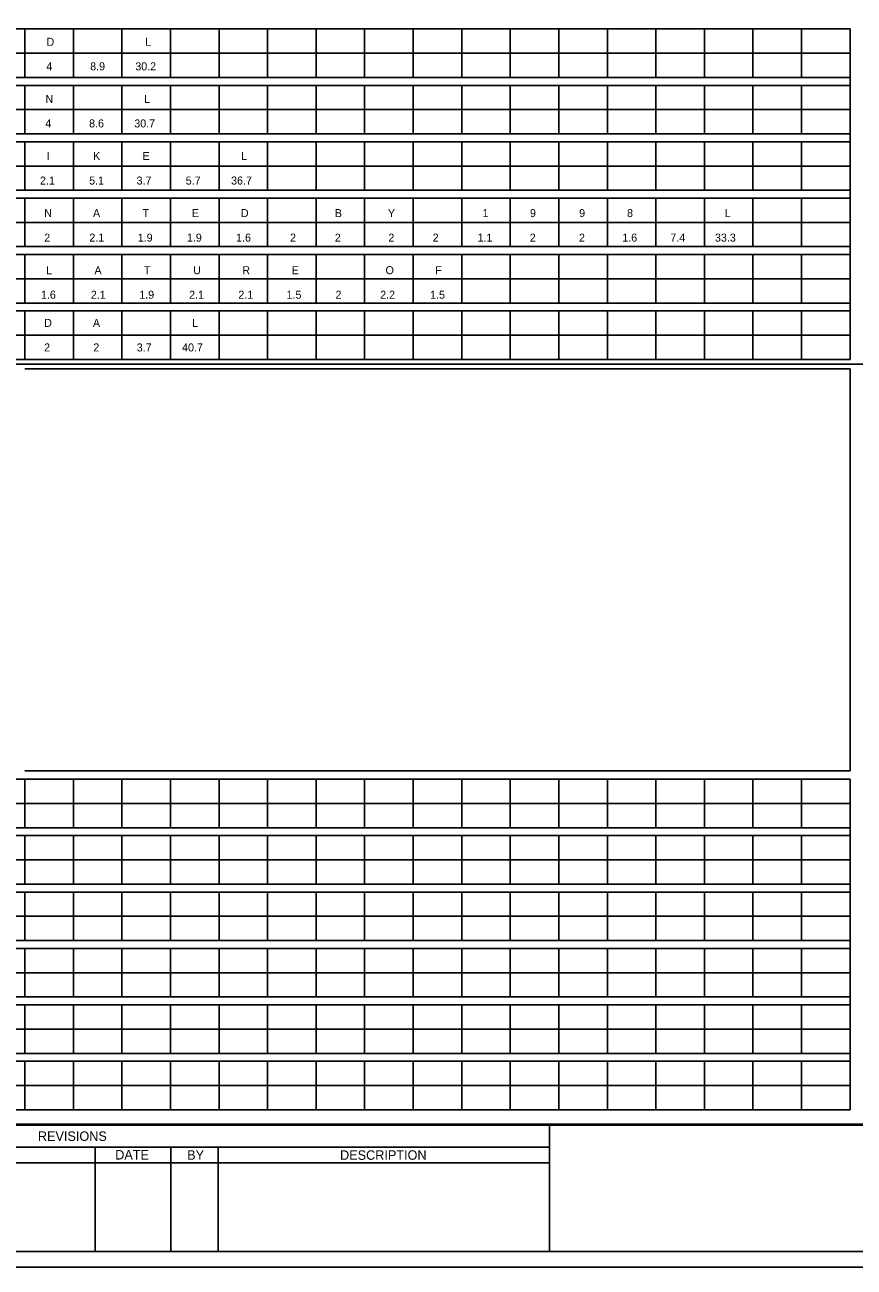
# Model space of a CAD drawing. Extents: x 17890628 to 17890844, y 17897693 to 17898031.
# Drawn here: x 17890726.4 to 17890772.1, y 17897907.6 to 17897976.1 of the extents above; entities that cross this region are included whole.
import ezdxf

# ---------------------------------------------------------------- set-up
doc = ezdxf.new("R2010")
doc.units = 0
for name, color, linetype in [('GSSign', 7, 'Continuous'), ('PlotBorder_dp', 7, 'Continuous'), ('SheetBorder_dp', 7, 'Continuous'), ('SheetLines_dp', 7, 'Continuous'), ('SheetLinesMisc2_dp', 7, 'Continuous'), ('TextMisc', 7, 'Continuous')]:
    doc.layers.add(name, color=color, linetype=linetype)

msp = doc.modelspace()

# ---------------------------------------------------------------- linework, layer by layer
at = {"layer": 'PlotBorder_dp'}
msp.add_lwpolyline([(17890700.471, 17897907.61), (17890843.989, 17897907.61), (17890843.989, 17897999.809), (17890700.471, 17897999.809)], close=True, dxfattribs=at)
at = {"layer": 'SheetBorder_dp'}
for p, q in [((17890705.254, 17897915.438), (17890839.205, 17897915.438)), ((17890705.254, 17897908.479), (17890839.205, 17897908.479))]:
    msp.add_line(p, q, dxfattribs=at)
at = {"layer": 'SheetLines_dp'}
for p, q in [((17890755.355, 17897915.438), (17890755.355, 17897908.479)), ((17890705.254, 17897914.22), (17890755.355, 17897914.22)), ((17890730.305, 17897914.22), (17890730.305, 17897908.479)), ((17890734.48, 17897914.22), (17890734.48, 17897908.479)), ((17890737.089, 17897914.22), (17890737.089, 17897908.479)), ((17890705.254, 17897913.35), (17890755.355, 17897913.35))]:
    msp.add_line(p, q, dxfattribs=at)
at = {"layer": 'SheetLinesMisc2_dp'}
for p, q in [((17890706.142, 17897975.843), (17890771.912, 17897975.843)), ((17890726.429, 17897975.843), (17890726.429, 17897973.171)), ((17890729.104, 17897975.843), (17890729.104, 17897973.171)), ((17890731.779, 17897975.843), (17890731.779, 17897973.171)), ((17890734.455, 17897975.843), (17890734.455, 17897973.171)), ((17890737.131, 17897975.843), (17890737.131, 17897973.171)), ((17890739.806, 17897975.843), (17890739.806, 17897973.171)), ((17890742.481, 17897975.843), (17890742.481, 17897973.171)), ((17890745.157, 17897975.843), (17890745.157, 17897973.171)), ((17890747.833, 17897975.843), (17890747.833, 17897973.171)), ((17890750.508, 17897975.843), (17890750.508, 17897973.171)), ((17890753.183, 17897975.843), (17890753.183, 17897973.171)), ((17890755.859, 17897975.843), (17890755.859, 17897973.171)), ((17890758.535, 17897975.843), (17890758.535, 17897973.171)), ((17890761.21, 17897975.843), (17890761.21, 17897973.171)), ((17890763.885, 17897975.843), (17890763.885, 17897973.171)), ((17890766.561, 17897975.843), (17890766.561, 17897973.171)), ((17890769.237, 17897975.843), (17890769.237, 17897973.171)), ((17890771.912, 17897957.633), (17890771.912, 17897975.843)), ((17890706.142, 17897974.507), (17890771.912, 17897974.507)), ((17890706.142, 17897973.171), (17890771.912, 17897973.171)), ((17890706.142, 17897972.735), (17890771.912, 17897972.735)), ((17890726.429, 17897972.735), (17890726.429, 17897970.064)), ((17890729.104, 17897972.735), (17890729.104, 17897970.064)), ((17890731.779, 17897972.735), (17890731.779, 17897970.064)), ((17890734.455, 17897972.735), (17890734.455, 17897970.064)), ((17890737.131, 17897972.735), (17890737.131, 17897970.064)), ((17890739.806, 17897972.735), (17890739.806, 17897970.064)), ((17890742.481, 17897972.735), (17890742.481, 17897970.064)), ((17890745.157, 17897972.735), (17890745.157, 17897970.064)), ((17890747.833, 17897972.735), (17890747.833, 17897970.064)), ((17890750.508, 17897972.735), (17890750.508, 17897970.064)), ((17890753.183, 17897972.735), (17890753.183, 17897970.064)), ((17890755.859, 17897972.735), (17890755.859, 17897970.064)), ((17890758.535, 17897972.735), (17890758.535, 17897970.064)), ((17890761.21, 17897972.735), (17890761.21, 17897970.064)), ((17890763.885, 17897972.735), (17890763.885, 17897970.064)), ((17890766.561, 17897972.735), (17890766.561, 17897970.064)), ((17890769.237, 17897972.735), (17890769.237, 17897970.064)), ((17890706.142, 17897971.399), (17890771.912, 17897971.4)), ((17890706.142, 17897970.064), (17890771.912, 17897970.064)), ((17890706.142, 17897969.628), (17890771.912, 17897969.628)), ((17890726.429, 17897969.628), (17890726.429, 17897966.956)), ((17890729.104, 17897969.628), (17890729.104, 17897966.956)), ((17890731.779, 17897969.628), (17890731.779, 17897966.956)), ((17890734.455, 17897969.628), (17890734.455, 17897966.956)), ((17890737.131, 17897969.628), (17890737.131, 17897966.956)), ((17890739.806, 17897969.628), (17890739.806, 17897966.956)), ((17890742.481, 17897969.628), (17890742.481, 17897966.956)), ((17890745.157, 17897969.628), (17890745.157, 17897966.956)), ((17890747.833, 17897969.628), (17890747.833, 17897966.956)), ((17890750.508, 17897969.628), (17890750.508, 17897966.956)), ((17890753.183, 17897969.628), (17890753.183, 17897966.956)), ((17890755.859, 17897969.628), (17890755.859, 17897966.956)), ((17890758.535, 17897969.628), (17890758.535, 17897966.956)), ((17890761.21, 17897969.628), (17890761.21, 17897966.956)), ((17890763.885, 17897969.628), (17890763.885, 17897966.956)), ((17890766.561, 17897969.628), (17890766.561, 17897966.956)), ((17890769.237, 17897969.628), (17890769.237, 17897966.956)), ((17890706.142, 17897968.292), (17890771.912, 17897968.292)), ((17890706.142, 17897966.956), (17890771.912, 17897966.956)), ((17890706.142, 17897966.52), (17890771.912, 17897966.52)), ((17890726.429, 17897966.52), (17890726.429, 17897963.848)), ((17890729.104, 17897966.52), (17890729.104, 17897963.848)), ((17890731.779, 17897966.52), (17890731.779, 17897963.848)), ((17890734.455, 17897966.52), (17890734.455, 17897963.848)), ((17890737.131, 17897966.52), (17890737.131, 17897963.848)), ((17890739.806, 17897966.52), (17890739.806, 17897963.848)), ((17890742.481, 17897966.52), (17890742.481, 17897963.848)), ((17890745.157, 17897966.52), (17890745.157, 17897963.848)), ((17890747.833, 17897966.52), (17890747.833, 17897963.848)), ((17890750.508, 17897966.52), (17890750.508, 17897963.848)), ((17890753.183, 17897966.52), (17890753.183, 17897963.848)), ((17890755.859, 17897966.52), (17890755.859, 17897963.848)), ((17890758.535, 17897966.52), (17890758.535, 17897963.848)), ((17890761.21, 17897966.52), (17890761.21, 17897963.848)), ((17890763.885, 17897966.52), (17890763.885, 17897963.848)), ((17890766.561, 17897966.52), (17890766.561, 17897963.848)), ((17890769.237, 17897966.52), (17890769.237, 17897963.848)), ((17890706.142, 17897965.184), (17890771.912, 17897965.184)), ((17890706.142, 17897963.848), (17890771.912, 17897963.848)), ((17890706.142, 17897963.412), (17890771.912, 17897963.412)), ((17890726.429, 17897963.412), (17890726.429, 17897960.74)), ((17890729.104, 17897963.412), (17890729.104, 17897960.74)), ((17890731.779, 17897963.412), (17890731.779, 17897960.74)), ((17890734.455, 17897963.412), (17890734.455, 17897960.74)), ((17890737.131, 17897963.412), (17890737.131, 17897960.74)), ((17890739.806, 17897963.412), (17890739.806, 17897960.74)), ((17890742.481, 17897963.412), (17890742.481, 17897960.74)), ((17890745.157, 17897963.412), (17890745.157, 17897960.74)), ((17890747.833, 17897963.412), (17890747.833, 17897960.74)), ((17890750.508, 17897963.412), (17890750.508, 17897960.74)), ((17890753.183, 17897963.412), (17890753.183, 17897960.74)), ((17890755.859, 17897963.412), (17890755.859, 17897960.74)), ((17890758.535, 17897963.412), (17890758.535, 17897960.74)), ((17890761.21, 17897963.412), (17890761.21, 17897960.74)), ((17890763.885, 17897963.412), (17890763.885, 17897960.74)), ((17890766.561, 17897963.412), (17890766.561, 17897960.74)), ((17890769.237, 17897963.412), (17890769.237, 17897960.74)), ((17890706.142, 17897962.076), (17890771.912, 17897962.076)), ((17890706.142, 17897960.74), (17890771.912, 17897960.74)), ((17890706.142, 17897960.304), (17890771.912, 17897960.304)), ((17890726.429, 17897960.304), (17890726.429, 17897957.633)), ((17890729.104, 17897960.304), (17890729.104, 17897957.633)), ((17890731.779, 17897960.304), (17890731.779, 17897957.633)), ((17890734.455, 17897960.304), (17890734.455, 17897957.633)), ((17890737.131, 17897960.304), (17890737.131, 17897957.633)), ((17890739.806, 17897960.304), (17890739.806, 17897957.633)), ((17890742.481, 17897960.304), (17890742.481, 17897957.633)), ((17890745.157, 17897960.304), (17890745.157, 17897957.633)), ((17890747.833, 17897960.304), (17890747.833, 17897957.633)), ((17890750.508, 17897960.304), (17890750.508, 17897957.633)), ((17890753.183, 17897960.304), (17890753.183, 17897957.633)), ((17890755.859, 17897960.304), (17890755.859, 17897957.633)), ((17890758.535, 17897960.304), (17890758.535, 17897957.633)), ((17890761.21, 17897960.304), (17890761.21, 17897957.633)), ((17890763.885, 17897960.304), (17890763.885, 17897957.633)), ((17890766.561, 17897960.304), (17890766.561, 17897957.633)), ((17890769.237, 17897960.304), (17890769.237, 17897957.633)), ((17890706.142, 17897958.969), (17890771.912, 17897958.969)), ((17890705.5, 17897957.37), (17890839.233, 17897957.37)), ((17890706.142, 17897957.633), (17890771.912, 17897957.633)), ((17890726.429, 17897957.108), (17890771.912, 17897957.108)), ((17890771.912, 17897934.985), (17890771.912, 17897957.109)), ((17890706.142, 17897934.497), (17890771.912, 17897934.497)), ((17890726.429, 17897934.953), (17890771.912, 17897934.953)), ((17890726.429, 17897934.497), (17890726.429, 17897931.825)), ((17890729.104, 17897934.497), (17890729.104, 17897931.825)), ((17890731.779, 17897934.497), (17890731.779, 17897931.825)), ((17890734.455, 17897934.497), (17890734.455, 17897931.825)), ((17890737.131, 17897934.497), (17890737.131, 17897931.825)), ((17890739.806, 17897934.497), (17890739.806, 17897931.825)), ((17890742.481, 17897934.497), (17890742.481, 17897931.825)), ((17890745.157, 17897934.497), (17890745.157, 17897931.825)), ((17890747.833, 17897934.497), (17890747.833, 17897931.825)), ((17890750.508, 17897934.497), (17890750.508, 17897931.825)), ((17890753.183, 17897934.497), (17890753.183, 17897931.825)), ((17890755.859, 17897934.497), (17890755.859, 17897931.825)), ((17890758.535, 17897934.497), (17890758.535, 17897931.825)), ((17890761.21, 17897934.497), (17890761.21, 17897931.825)), ((17890763.885, 17897934.497), (17890763.885, 17897931.825)), ((17890766.561, 17897934.497), (17890766.561, 17897931.825)), ((17890769.237, 17897934.497), (17890769.237, 17897931.825)), ((17890771.912, 17897934.955), (17890771.912, 17897934.985)), ((17890771.912, 17897916.286), (17890771.912, 17897934.497)), ((17890706.142, 17897933.162), (17890771.912, 17897933.162)), ((17890706.142, 17897931.825), (17890771.912, 17897931.825)), ((17890706.142, 17897931.389), (17890771.912, 17897931.389)), ((17890726.429, 17897931.389), (17890726.429, 17897928.717)), ((17890729.104, 17897931.389), (17890729.104, 17897928.717)), ((17890731.779, 17897931.389), (17890731.779, 17897928.717)), ((17890734.455, 17897931.389), (17890734.455, 17897928.717)), ((17890737.131, 17897931.389), (17890737.131, 17897928.717)), ((17890739.806, 17897931.389), (17890739.806, 17897928.717)), ((17890742.481, 17897931.389), (17890742.481, 17897928.717)), ((17890745.157, 17897931.389), (17890745.157, 17897928.717)), ((17890747.833, 17897931.389), (17890747.833, 17897928.717)), ((17890750.508, 17897931.389), (17890750.508, 17897928.717)), ((17890753.183, 17897931.389), (17890753.183, 17897928.717)), ((17890755.859, 17897931.389), (17890755.859, 17897928.717)), ((17890758.535, 17897931.389), (17890758.535, 17897928.717)), ((17890761.21, 17897931.389), (17890761.21, 17897928.717)), ((17890763.885, 17897931.389), (17890763.885, 17897928.717)), ((17890766.561, 17897931.389), (17890766.561, 17897928.717)), ((17890769.237, 17897931.389), (17890769.237, 17897928.717)), ((17890706.142, 17897930.053), (17890771.912, 17897930.053)), ((17890706.142, 17897928.717), (17890771.912, 17897928.717)), ((17890706.142, 17897928.281), (17890771.912, 17897928.281)), ((17890726.429, 17897928.281), (17890726.429, 17897925.609)), ((17890729.104, 17897928.281), (17890729.104, 17897925.609)), ((17890731.779, 17897928.281), (17890731.779, 17897925.609)), ((17890734.455, 17897928.281), (17890734.455, 17897925.609)), ((17890737.131, 17897928.281), (17890737.131, 17897925.609)), ((17890739.806, 17897928.281), (17890739.806, 17897925.609)), ((17890742.481, 17897928.281), (17890742.481, 17897925.609)), ((17890745.157, 17897928.281), (17890745.157, 17897925.609)), ((17890747.833, 17897928.281), (17890747.833, 17897925.609)), ((17890750.508, 17897928.281), (17890750.508, 17897925.609)), ((17890753.183, 17897928.281), (17890753.183, 17897925.609)), ((17890755.859, 17897928.281), (17890755.859, 17897925.609)), ((17890758.535, 17897928.281), (17890758.535, 17897925.609)), ((17890761.21, 17897928.281), (17890761.21, 17897925.609)), ((17890763.885, 17897928.281), (17890763.885, 17897925.609)), ((17890766.561, 17897928.281), (17890766.561, 17897925.609)), ((17890769.237, 17897928.281), (17890769.237, 17897925.609)), ((17890706.142, 17897926.945), (17890771.912, 17897926.945)), ((17890706.142, 17897925.609), (17890771.912, 17897925.609)), ((17890706.142, 17897925.173), (17890771.912, 17897925.173)), ((17890726.429, 17897925.173), (17890726.429, 17897922.501)), ((17890729.104, 17897925.173), (17890729.104, 17897922.501)), ((17890731.779, 17897925.173), (17890731.779, 17897922.501)), ((17890734.455, 17897925.173), (17890734.455, 17897922.501)), ((17890737.131, 17897925.173), (17890737.131, 17897922.501)), ((17890739.806, 17897925.173), (17890739.806, 17897922.501)), ((17890742.481, 17897925.173), (17890742.481, 17897922.501)), ((17890745.157, 17897925.173), (17890745.157, 17897922.501)), ((17890747.833, 17897925.173), (17890747.833, 17897922.501)), ((17890750.508, 17897925.173), (17890750.508, 17897922.501)), ((17890753.183, 17897925.173), (17890753.183, 17897922.501)), ((17890755.859, 17897925.173), (17890755.859, 17897922.501)), ((17890758.535, 17897925.173), (17890758.535, 17897922.501)), ((17890761.21, 17897925.173), (17890761.21, 17897922.501)), ((17890763.885, 17897925.173), (17890763.885, 17897922.501)), ((17890766.561, 17897925.173), (17890766.561, 17897922.501)), ((17890769.237, 17897925.173), (17890769.237, 17897922.501)), ((17890706.142, 17897923.838), (17890771.912, 17897923.838)), ((17890706.142, 17897922.501), (17890771.912, 17897922.501)), ((17890706.142, 17897922.065), (17890771.912, 17897922.065)), ((17890726.429, 17897922.065), (17890726.429, 17897919.393)), ((17890729.104, 17897922.065), (17890729.104, 17897919.393)), ((17890731.779, 17897922.065), (17890731.779, 17897919.393)), ((17890734.455, 17897922.065), (17890734.455, 17897919.393)), ((17890737.131, 17897922.065), (17890737.131, 17897919.393)), ((17890739.806, 17897922.065), (17890739.806, 17897919.393)), ((17890742.481, 17897922.065), (17890742.481, 17897919.393)), ((17890745.157, 17897922.065), (17890745.157, 17897919.393)), ((17890747.833, 17897922.065), (17890747.833, 17897919.393)), ((17890750.508, 17897922.065), (17890750.508, 17897919.393)), ((17890753.183, 17897922.065), (17890753.183, 17897919.393)), ((17890755.859, 17897922.065), (17890755.859, 17897919.393)), ((17890758.535, 17897922.065), (17890758.535, 17897919.393)), ((17890761.21, 17897922.065), (17890761.21, 17897919.393)), ((17890763.885, 17897922.065), (17890763.885, 17897919.393)), ((17890766.561, 17897922.065), (17890766.561, 17897919.393)), ((17890769.237, 17897922.065), (17890769.237, 17897919.393)), ((17890706.142, 17897920.729), (17890771.912, 17897920.729)), ((17890706.142, 17897919.393), (17890771.912, 17897919.393)), ((17890706.142, 17897918.958), (17890771.912, 17897918.958)), ((17890726.429, 17897918.958), (17890726.429, 17897916.286)), ((17890729.104, 17897918.958), (17890729.104, 17897916.286)), ((17890731.779, 17897918.958), (17890731.779, 17897916.286)), ((17890734.455, 17897918.958), (17890734.455, 17897916.286)), ((17890737.131, 17897918.958), (17890737.131, 17897916.286)), ((17890739.806, 17897918.958), (17890739.806, 17897916.286)), ((17890742.481, 17897918.958), (17890742.481, 17897916.286)), ((17890745.157, 17897918.958), (17890745.157, 17897916.286)), ((17890747.833, 17897918.958), (17890747.833, 17897916.286)), ((17890750.508, 17897918.958), (17890750.508, 17897916.286)), ((17890753.183, 17897918.958), (17890753.183, 17897916.286)), ((17890755.859, 17897918.958), (17890755.859, 17897916.286)), ((17890758.535, 17897918.958), (17890758.535, 17897916.286)), ((17890761.21, 17897918.958), (17890761.21, 17897916.286)), ((17890763.885, 17897918.958), (17890763.885, 17897916.286)), ((17890766.561, 17897918.958), (17890766.561, 17897916.286)), ((17890769.237, 17897918.958), (17890769.237, 17897916.286)), ((17890706.142, 17897917.622), (17890771.912, 17897917.622)), ((17890706.142, 17897916.286), (17890771.912, 17897916.286)), ((17890705.5, 17897915.484), (17890839.233, 17897915.484))]:
    msp.add_line(p, q, dxfattribs=at)

# ---------------------------------------------------------------- texts
at = {"layer": 'GSSign'}
for s, height, p in [('D', 0.441, (17890727.625, 17897974.917)), ('L', 0.441, (17890733.065, 17897974.917)), ('4', 0.441, (17890727.614, 17897973.564)), ('8.9', 0.4411, (17890730.03, 17897973.564)), ('30.2', 0.4411, (17890732.518, 17897973.564)), ('N', 0.441, (17890727.566, 17897971.77)), ('L', 0.441, (17890733.006, 17897971.77)), ('4', 0.441, (17890727.556, 17897970.418)), ('8.6', 0.4411, (17890729.971, 17897970.418)), ('30.7', 0.4411, (17890732.46, 17897970.418)), ('I', 0.441, (17890727.632, 17897968.624)), ('K', 0.441, (17890730.194, 17897968.624)), ('E', 0.441, (17890732.914, 17897968.624)), ('L', 0.441, (17890738.343, 17897968.624)), ('2.1', 0.4411, (17890727.264, 17897967.271)), ('5.1', 0.4411, (17890729.973, 17897967.271)), ('3.7', 0.4411, (17890732.588, 17897967.271)), ('5.7', 0.4411, (17890735.297, 17897967.271)), ('36.7', 0.4411, (17890737.797, 17897967.271)), ('N', 0.441, (17890727.496, 17897965.477)), ('A', 0.441, (17890730.185, 17897965.477)), ('T', 0.441, (17890732.915, 17897965.477)), ('E', 0.441, (17890735.635, 17897965.477)), ('D', 0.441, (17890738.334, 17897965.477)), ('B', 0.441, (17890743.515, 17897965.477)), ('Y', 0.441, (17890746.441, 17897965.477)), ('1', 0.441, (17890751.654, 17897965.477)), ('9', 0.441, (17890754.272, 17897965.477)), ('9', 0.441, (17890756.981, 17897965.477)), ('8', 0.441, (17890759.621, 17897965.477)), ('L', 0.441, (17890765.013, 17897965.477)), ('2', 0.441, (17890727.496, 17897964.125)), ('2.1', 0.4411, (17890729.985, 17897964.125)), ('1.9', 0.4411, (17890732.652, 17897964.125)), ('1.9', 0.4411, (17890735.362, 17897964.125)), ('1.6', 0.4411, (17890738.071, 17897964.125)), ('2', 0.441, (17890741.043, 17897964.125)), ('2', 0.441, (17890743.515, 17897964.125)), ('2', 0.441, (17890746.462, 17897964.125)), ('2', 0.441, (17890748.91, 17897964.125)), ('1.1', 0.4411, (17890751.381, 17897964.125)), ('2', 0.441, (17890754.261, 17897964.125)), ('2', 0.441, (17890756.97, 17897964.125)), ('1.6', 0.4411, (17890759.358, 17897964.125)), ('7.4', 0.4411, (17890762.006, 17897964.125)), ('33.3', 0.4411, (17890764.467, 17897964.125)), ('L', 0.441, (17890727.599, 17897962.33)), ('A', 0.441, (17890730.266, 17897962.33)), ('T', 0.441, (17890732.997, 17897962.33)), ('U', 0.441, (17890735.706, 17897962.33)), ('R', 0.441, (17890738.415, 17897962.33)), ('E', 0.441, (17890741.135, 17897962.33)), ('O', 0.441, (17890746.309, 17897962.33)), ('F', 0.441, (17890749.05, 17897962.33)), ('1.6', 0.4411, (17890727.316, 17897960.978)), ('2.1', 0.4411, (17890730.067, 17897960.978)), ('1.9', 0.4411, (17890732.734, 17897960.978)), ('2.1', 0.4411, (17890735.486, 17897960.978)), ('2.1', 0.4411, (17890738.195, 17897960.978)), ('1.5', 0.4411, (17890740.852, 17897960.978)), ('2', 0.441, (17890743.551, 17897960.978)), ('2.2', 0.4411, (17890746.015, 17897960.978)), ('1.5', 0.4411, (17890748.766, 17897960.978)), ('D', 0.441, (17890727.493, 17897959.426)), ('A', 0.441, (17890730.181, 17897959.426)), ('L', 0.441, (17890735.642, 17897959.426)), ('2', 0.441, (17890727.493, 17897958.074)), ('2', 0.441, (17890730.202, 17897958.074)), ('3.7', 0.4411, (17890732.597, 17897958.074)), ('40.7', 0.4411, (17890735.096, 17897958.074))]:
    msp.add_text(s, height=height, dxfattribs=at).set_placement(p)
at = {"layer": 'TextMisc'}
for s, p in [('REVISIONS', (17890727.148, 17897914.568)), ('BY', (17890735.376, 17897913.533))]:
    msp.add_text(s, height=0.5219, dxfattribs=at).set_placement(p)
for s, height, rotation, p in [('DATE', 0.5219, 359.86925, (17890731.41, 17897913.542)), ('DESCRIPTION', 0.52178, 0.04975, (17890743.804, 17897913.524))]:
    msp.add_text(s, height=height, rotation=rotation, dxfattribs=at).set_placement(p)

doc.saveas('drawing.dxf')
